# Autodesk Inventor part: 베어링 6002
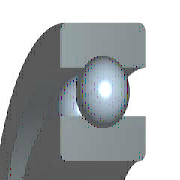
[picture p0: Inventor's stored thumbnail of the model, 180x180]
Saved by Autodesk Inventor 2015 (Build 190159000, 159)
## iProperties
IsCustomPart: 0
Created: 2012-02
Part Number: 베어링 6002
Material: 강철, 연강
Description: 깊은 그루브 볼 베어링
Document SubType Name: Modeling
Standard: KS B 2023
Designer: mduedu
Standards Organization: KS
Language: ko-KR
Size Designation: 6002 - 15 x 32 x 9
Categories: <MemberInstance><Categories><Category DisplayName="샤프트 부품" InternalName="7f7aeb1f-a693-4053-b835-cee3144e0d98" Mnemonic="SHFT"><Category DisplayName="베어링" Inter
Density: 1 g/cm^3
Appearance: 노란색
Author: mduedu
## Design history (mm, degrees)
sketch "스케치" dims "d0" = 4.42 (= -0.26 x WD + 0.26 x BD)
  geometry: L1 (2.29, 11.75)-(6.71, 11.75); L2 (4.5, 11.75)-(4.5, 9.54); L3 (4.5, 11.75)-(4.5, 13.96); L4 (2.858, 10.271)-(0, 10.271); L5 (0, 7.5)-(9, 7.5); L6 (2.858, 13.229)-(0, 13.229); L7 (0, 16)-(9, 16); L8 (9, 7.5)-(9, 10.271); L9 (6.142, 10.271)-(9, 10.271); L10 (6.142, 13.229)-(9, 13.229); L11 (9, 16)-(9, 13.229); L12 (-1.4, 0)-(8.4, 0) reference; L13 (0, -0.3)-(0, 5.3) reference
  constraints: 22 end point, 4 point on line, 2 collinear, 2 perpendicular, 2 symmetric about line, 1 midpoint, 1 parallel, 14 other
  dimensions: "d9" = 15 diameter of L5 L12 (= WD); "d11" = 32 diameter of L7 L12 (= BD); "d12" = 9 distance between parallel lines of L8 L13 (= KB); "d13" = 20.542 diameter of L9 L12 (= 0.326 x BD + 0.674 x WD)
revolve "본체" stored, may be unused: angle "d6" = 90 deg
revolve "볼" stored, may be unused: angle "d7" = 90 deg
pattern_circular "IDS_ARRAYBALL[SIMPL:T]" dims angle "d3" = 360 deg
body "Solid1"
fillet "모깎기1" dims "d1" = 0.3 (= KRS)
other parameters: "WD" = 15 [user parameter; used in 5 equation terms], "BD" = 32 [user parameter; used in 5 equation terms], "KB" = 9 [user parameter; used in 1 equation term], "KRS" = 0.3 [user parameter; used in 1 equation term], "d4" = 0, "d5" = 0, "d8" = 0, "d14" = 0, "d15" = 0, "BBA" = 0 [user parameter], "BC0" = 2850000 [user parameter], "BC" = 5590000 [user parameter], "BR" = 16 (= 0.5 x BD) [user parameter], "WR" = 7.5 (= 0.5 x WD) [user parameter]
